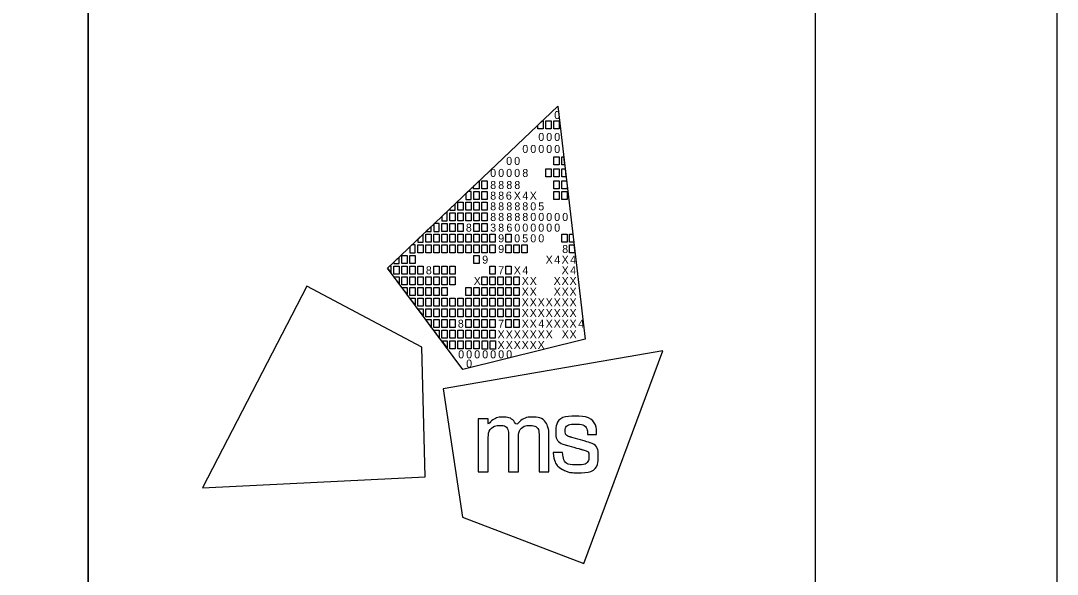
# Model space of a CAD drawing. Extents: x -0.2 to 34, y 0 to 22.
# Drawn here: x 31.86 to 34, y 3.12 to 4.263 of the extents above; entities that cross this region are included whole.
import ezdxf

# ---------------------------------------------------------------- set-up
doc = ezdxf.new("R2010")
doc.units = 0
for name, color, linetype in [('SC_Scratch1', 7, 'Continuous'), ('SH_Border', 7, 'Continuous'), ('SH_Cut_Line', 7, 'Continuous'), ('SH_Data', 7, 'Continuous')]:
    doc.layers.add(name, color=color, linetype=linetype)

msp = doc.modelspace()

# ---------------------------------------------------------------- linework, layer by layer
at = {"layer": 'SC_Scratch1'}
msp.add_lwpolyline([(1.5, 21.5), (32, 21.5), (32, 0.5), (1.5, 0.5)], close=True, dxfattribs=at)
at = {"layer": 'SH_Border'}
msp.add_line((32, 0.5), (32, 21.5), dxfattribs=at)
msp.add_lwpolyline([(1.5, 21.5), (33.5, 21.5), (33.5, 0.5), (1.5, 0.5)], close=True, dxfattribs=at)
at = {"layer": 'SH_Cut_Line'}
msp.add_lwpolyline([(0, 0), (34, 0), (34, 22), (0, 22)], close=True, dxfattribs=at)
at = {"layer": 'SH_Data'}
for p, q in [((32.6175, 3.7519), (32.9688, 4.0861)), ((32.9688, 4.0861), (32.9688, 4.0861)), ((32.9688, 4.0861), (33.0253, 3.6052)), ((32.773, 3.543), (32.6175, 3.7519)), ((33.0253, 3.6052), (32.773, 3.543)), ((32.75, 3.5), (32.75, 3.5))]:
    msp.add_line(p, q, dxfattribs=at)
for points in [[(32.9279, 4.0472), (32.9369, 4.0558), (32.9389, 4.0558), (32.9389, 4.0393), (32.9279, 4.0393)], [(32.9444, 4.0558), (32.9554, 4.0558), (32.9554, 4.0393), (32.9444, 4.0393)], [(32.9609, 4.0558), (32.9719, 4.0558), (32.9719, 4.0393), (32.9609, 4.0393)], [(32.9606, 3.9815), (32.9716, 3.9815), (32.9716, 3.965), (32.9606, 3.965)], [(32.9771, 3.9815), (32.9811, 3.9815), (32.983, 3.965), (32.9771, 3.965)], [(32.9441, 3.9567), (32.9551, 3.9567), (32.9551, 3.9402), (32.9441, 3.9402)], [(32.9606, 3.9567), (32.9716, 3.9567), (32.9716, 3.9402), (32.9606, 3.9402)], [(32.9771, 3.9567), (32.984, 3.9567), (32.9859, 3.9402), (32.9771, 3.9402)], [(32.7953, 3.9211), (32.8064, 3.9316), (32.8064, 3.9154), (32.7953, 3.9154)], [(32.8123, 3.9319), (32.8233, 3.9319), (32.8233, 3.9154), (32.8123, 3.9154)], [(32.9606, 3.9319), (32.9716, 3.9319), (32.9716, 3.9154), (32.9606, 3.9154)], [(32.9771, 3.9319), (32.9869, 3.9319), (32.9881, 3.9218), (32.9881, 3.9154), (32.9771, 3.9154)], [(32.7958, 3.9099), (32.8068, 3.9099), (32.8068, 3.8934), (32.7958, 3.8934)], [(32.8123, 3.9099), (32.8233, 3.9099), (32.8233, 3.8934), (32.8123, 3.8934)], [(32.9606, 3.9099), (32.9716, 3.9099), (32.9716, 3.8934), (32.9606, 3.8934)], [(32.9771, 3.9099), (32.9881, 3.9099), (32.9881, 3.8934), (32.9771, 3.8934)], [(32.7627, 3.8879), (32.7737, 3.8879), (32.7737, 3.8714), (32.7627, 3.8714)], [(32.7793, 3.8879), (32.7903, 3.8879), (32.7903, 3.8714), (32.7793, 3.8714)], [(32.7958, 3.8879), (32.8068, 3.8879), (32.8068, 3.8714), (32.7958, 3.8714)], [(32.8123, 3.8879), (32.8233, 3.8879), (32.8233, 3.8714), (32.8123, 3.8714)], [(32.7462, 3.8659), (32.7572, 3.8659), (32.7572, 3.8494), (32.7462, 3.8494)], [(32.7627, 3.8659), (32.7737, 3.8659), (32.7737, 3.8494), (32.7627, 3.8494)], [(32.7793, 3.8659), (32.7903, 3.8659), (32.7903, 3.8494), (32.7793, 3.8494)], [(32.7958, 3.8659), (32.8068, 3.8659), (32.8068, 3.8494), (32.7958, 3.8494)], [(32.8123, 3.8659), (32.8233, 3.8659), (32.8233, 3.8494), (32.8123, 3.8494)], [(32.7297, 3.8439), (32.7407, 3.8439), (32.7407, 3.8273), (32.7297, 3.8273)], [(32.7462, 3.8439), (32.7572, 3.8439), (32.7572, 3.8273), (32.7462, 3.8273)], [(32.7627, 3.8439), (32.7737, 3.8439), (32.7737, 3.8273), (32.7627, 3.8273)], [(32.7958, 3.8439), (32.8068, 3.8439), (32.8068, 3.8273), (32.7958, 3.8273)], [(32.8123, 3.8439), (32.8233, 3.8439), (32.8233, 3.8273), (32.8123, 3.8273)], [(32.6967, 3.8218), (32.7077, 3.8218), (32.7077, 3.8053), (32.6967, 3.8053)], [(32.7132, 3.8218), (32.7242, 3.8218), (32.7242, 3.8053), (32.7132, 3.8053)], [(32.7297, 3.8218), (32.7407, 3.8218), (32.7407, 3.8053), (32.7297, 3.8053)], [(32.7462, 3.8218), (32.7572, 3.8218), (32.7572, 3.8053), (32.7462, 3.8053)], [(32.7627, 3.8218), (32.7737, 3.8218), (32.7737, 3.8053), (32.7627, 3.8053)], [(32.7793, 3.8218), (32.7903, 3.8218), (32.7903, 3.8053), (32.7793, 3.8053)], [(32.7958, 3.8218), (32.8068, 3.8218), (32.8068, 3.8053), (32.7958, 3.8053)], [(32.8123, 3.8218), (32.8233, 3.8218), (32.8233, 3.8053), (32.8123, 3.8053)], [(32.8288, 3.8218), (32.8398, 3.8218), (32.8398, 3.8053), (32.8288, 3.8053)], [(32.8618, 3.8218), (32.8728, 3.8218), (32.8728, 3.8053), (32.8618, 3.8053)], [(32.9771, 3.8218), (32.9881, 3.8218), (32.9881, 3.8053), (32.9771, 3.8053)], [(32.9935, 3.8218), (32.9998, 3.8218), (33.0018, 3.8053), (32.9935, 3.8053)], [(32.6802, 3.7998), (32.6912, 3.7998), (32.6912, 3.7833), (32.6802, 3.7833)], [(32.6967, 3.7998), (32.7077, 3.7998), (32.7077, 3.7833), (32.6967, 3.7833)], [(32.7132, 3.7998), (32.7242, 3.7998), (32.7242, 3.7833), (32.7132, 3.7833)], [(32.7297, 3.7998), (32.7407, 3.7998), (32.7407, 3.7833), (32.7297, 3.7833)], [(32.7462, 3.7998), (32.7572, 3.7998), (32.7572, 3.7833), (32.7462, 3.7833)], [(32.7627, 3.7998), (32.7737, 3.7998), (32.7737, 3.7833), (32.7627, 3.7833)], [(32.7793, 3.7998), (32.7903, 3.7998), (32.7903, 3.7833), (32.7793, 3.7833)], [(32.7958, 3.7998), (32.8068, 3.7998), (32.8068, 3.7833), (32.7958, 3.7833)], [(32.8123, 3.7998), (32.8233, 3.7998), (32.8233, 3.7833), (32.8123, 3.7833)], [(32.8288, 3.7998), (32.8398, 3.7998), (32.8398, 3.7833), (32.8288, 3.7833)], [(32.8618, 3.7998), (32.8728, 3.7998), (32.8728, 3.7833), (32.8618, 3.7833)], [(32.8783, 3.7998), (32.8893, 3.7998), (32.8893, 3.7833), (32.8783, 3.7833)], [(32.8947, 3.7998), (32.9057, 3.7998), (32.9057, 3.7833), (32.8947, 3.7833)], [(32.9935, 3.7998), (33.0024, 3.7998), (33.0044, 3.7833), (32.9935, 3.7833)], [(32.6471, 3.7778), (32.6581, 3.7778), (32.6581, 3.7613), (32.6471, 3.7613)], [(32.6637, 3.7778), (32.6747, 3.7778), (32.6747, 3.7613), (32.6637, 3.7613)], [(32.7958, 3.7778), (32.8068, 3.7778), (32.8068, 3.7613), (32.7958, 3.7613)], [(32.6306, 3.7558), (32.6416, 3.7558), (32.6416, 3.7393), (32.6306, 3.7393)], [(32.6471, 3.7558), (32.6581, 3.7558), (32.6581, 3.7393), (32.6471, 3.7393)], [(32.6637, 3.7558), (32.6747, 3.7558), (32.6747, 3.7393), (32.6637, 3.7393)], [(32.6802, 3.7558), (32.6912, 3.7558), (32.6912, 3.7393), (32.6802, 3.7393)], [(32.7132, 3.7558), (32.7242, 3.7558), (32.7242, 3.7393), (32.7132, 3.7393)], [(32.7297, 3.7558), (32.7407, 3.7558), (32.7407, 3.7393), (32.7297, 3.7393)], [(32.7462, 3.7558), (32.7572, 3.7558), (32.7572, 3.7393), (32.7462, 3.7393)], [(32.8288, 3.7558), (32.8398, 3.7558), (32.8398, 3.7393), (32.8288, 3.7393)], [(32.8618, 3.7558), (32.8728, 3.7558), (32.8728, 3.7393), (32.8618, 3.7393)], [(32.6306, 3.7338), (32.6416, 3.7338), (32.6416, 3.72)], [(32.6471, 3.7338), (32.6581, 3.7338), (32.6581, 3.7173), (32.6471, 3.7173)], [(32.6637, 3.7338), (32.6747, 3.7338), (32.6747, 3.7173), (32.6637, 3.7173)], [(32.6802, 3.7338), (32.6912, 3.7338), (32.6912, 3.7173), (32.6802, 3.7173)], [(32.6967, 3.7338), (32.7077, 3.7338), (32.7077, 3.7173), (32.6967, 3.7173)], [(32.7132, 3.7338), (32.7242, 3.7338), (32.7242, 3.7173), (32.7132, 3.7173)], [(32.7297, 3.7338), (32.7407, 3.7338), (32.7407, 3.7173), (32.7297, 3.7173)], [(32.7462, 3.7338), (32.7572, 3.7338), (32.7572, 3.7173), (32.7462, 3.7173)], [(32.8123, 3.7338), (32.8233, 3.7338), (32.8233, 3.7173), (32.8123, 3.7173)], [(32.8288, 3.7338), (32.8398, 3.7338), (32.8398, 3.7173), (32.8288, 3.7173)], [(32.8453, 3.7338), (32.8563, 3.7338), (32.8563, 3.7173), (32.8453, 3.7173)], [(32.8618, 3.7338), (32.8728, 3.7338), (32.8728, 3.7173), (32.8618, 3.7173)], [(32.8783, 3.7338), (32.8893, 3.7338), (32.8893, 3.7173), (32.8783, 3.7173)], [(32.6471, 3.7117), (32.6581, 3.7117), (32.6581, 3.698)], [(32.6637, 3.7117), (32.6747, 3.7117), (32.6747, 3.6952), (32.6637, 3.6952)], [(32.6802, 3.7117), (32.6912, 3.7117), (32.6912, 3.6952), (32.6802, 3.6952)], [(32.6967, 3.7117), (32.7077, 3.7117), (32.7077, 3.6952), (32.6967, 3.6952)], [(32.7132, 3.7117), (32.7242, 3.7117), (32.7242, 3.6952), (32.7132, 3.6952)], [(32.7297, 3.7117), (32.7407, 3.7117), (32.7407, 3.6952), (32.7297, 3.6952)], [(32.7793, 3.7117), (32.7903, 3.7117), (32.7903, 3.6952), (32.7793, 3.6952)], [(32.7958, 3.7117), (32.8068, 3.7117), (32.8068, 3.6952), (32.7958, 3.6952)], [(32.8123, 3.7117), (32.8233, 3.7117), (32.8233, 3.6952), (32.8123, 3.6952)], [(32.8288, 3.7117), (32.8398, 3.7117), (32.8398, 3.6952), (32.8288, 3.6952)], [(32.8453, 3.7117), (32.8563, 3.7117), (32.8563, 3.6952), (32.8453, 3.6952)], [(32.8618, 3.7117), (32.8728, 3.7117), (32.8728, 3.6952), (32.8618, 3.6952)], [(32.8783, 3.7117), (32.8893, 3.7117), (32.8893, 3.6952), (32.8783, 3.6952)], [(32.6637, 3.6897), (32.6747, 3.6897), (32.6747, 3.676)], [(32.6747, 3.6897), (32.6747, 3.6897), (32.6747, 3.6897)], [(32.6802, 3.6897), (32.6912, 3.6897), (32.6912, 3.6732), (32.6802, 3.6732)], [(32.6967, 3.6897), (32.7077, 3.6897), (32.7077, 3.6732), (32.6967, 3.6732)], [(32.7132, 3.6897), (32.7242, 3.6897), (32.7242, 3.6732), (32.7132, 3.6732)], [(32.7297, 3.6897), (32.7407, 3.6897), (32.7407, 3.6732), (32.7297, 3.6732)], [(32.7462, 3.6897), (32.7572, 3.6897), (32.7572, 3.6732), (32.7462, 3.6732)], [(32.7627, 3.6897), (32.7737, 3.6897), (32.7737, 3.6732), (32.7627, 3.6732)], [(32.7793, 3.6897), (32.7903, 3.6897), (32.7903, 3.6732), (32.7793, 3.6732)], [(32.7958, 3.6897), (32.8068, 3.6897), (32.8068, 3.6732), (32.7958, 3.6732)], [(32.8123, 3.6897), (32.8233, 3.6897), (32.8233, 3.6732), (32.8123, 3.6732)], [(32.8288, 3.6897), (32.8398, 3.6897), (32.8398, 3.6732), (32.8288, 3.6732)], [(32.8453, 3.6897), (32.8563, 3.6897), (32.8563, 3.6732), (32.8453, 3.6732)], [(32.8618, 3.6897), (32.8728, 3.6897), (32.8728, 3.6732), (32.8618, 3.6732)], [(32.8783, 3.6897), (32.8893, 3.6897), (32.8893, 3.6732), (32.8783, 3.6732)], [(32.6802, 3.6677), (32.6912, 3.6677), (32.6912, 3.654)], [(32.6967, 3.6677), (32.7077, 3.6677), (32.7077, 3.6512), (32.6967, 3.6512)], [(32.7132, 3.6677), (32.7242, 3.6677), (32.7242, 3.6512), (32.7132, 3.6512)], [(32.7297, 3.6677), (32.7407, 3.6677), (32.7407, 3.6512), (32.7297, 3.6512)], [(32.7462, 3.6677), (32.7572, 3.6677), (32.7572, 3.6512), (32.7462, 3.6512)], [(32.7627, 3.6677), (32.7737, 3.6677), (32.7737, 3.6512), (32.7627, 3.6512)], [(32.7793, 3.6677), (32.7903, 3.6677), (32.7903, 3.6512), (32.7793, 3.6512)], [(32.7958, 3.6677), (32.8068, 3.6677), (32.8068, 3.6512), (32.7958, 3.6512)], [(32.8123, 3.6677), (32.8233, 3.6677), (32.8233, 3.6512), (32.8123, 3.6512)], [(32.8288, 3.6677), (32.8398, 3.6677), (32.8398, 3.6512), (32.8288, 3.6512)], [(32.8453, 3.6677), (32.8563, 3.6677), (32.8563, 3.6512), (32.8453, 3.6512)], [(32.8618, 3.6677), (32.8728, 3.6677), (32.8728, 3.6512), (32.8618, 3.6512)], [(32.8783, 3.6677), (32.8893, 3.6677), (32.8893, 3.6512), (32.8783, 3.6512)], [(32.7077, 3.6305), (32.6965, 3.6457), (32.7077, 3.6457)], [(32.7132, 3.6457), (32.7242, 3.6457), (32.7242, 3.6292), (32.7132, 3.6292)], [(32.7297, 3.6457), (32.7407, 3.6457), (32.7407, 3.6292), (32.7297, 3.6292)], [(32.7462, 3.6457), (32.7572, 3.6457), (32.7572, 3.6292), (32.7462, 3.6292)], [(32.7793, 3.6457), (32.7903, 3.6457), (32.7903, 3.6292), (32.7793, 3.6292)], [(32.7958, 3.6457), (32.8068, 3.6457), (32.8068, 3.6292), (32.7958, 3.6292)], [(32.8123, 3.6457), (32.8233, 3.6457), (32.8233, 3.6292), (32.8123, 3.6292)], [(32.8288, 3.6457), (32.8398, 3.6457), (32.8398, 3.6292), (32.8288, 3.6292)], [(32.8618, 3.6457), (32.8728, 3.6457), (32.8728, 3.6292), (32.8618, 3.6292)], [(32.8783, 3.6457), (32.8893, 3.6457), (32.8893, 3.6292), (32.8783, 3.6292)], [(32.724, 3.6082), (32.7132, 3.6237), (32.7242, 3.6237)], [(32.7297, 3.6237), (32.7407, 3.6237), (32.7407, 3.6072), (32.7297, 3.6072)], [(32.7462, 3.6237), (32.7572, 3.6237), (32.7572, 3.6072), (32.7462, 3.6072)], [(32.7627, 3.6237), (32.7737, 3.6237), (32.7737, 3.6072), (32.7627, 3.6072)], [(32.7793, 3.6237), (32.7903, 3.6237), (32.7903, 3.6072), (32.7793, 3.6072)], [(32.7958, 3.6237), (32.8068, 3.6237), (32.8068, 3.6072), (32.7958, 3.6072)], [(32.8123, 3.6237), (32.8233, 3.6237), (32.8233, 3.6072), (32.8123, 3.6072)], [(32.8288, 3.6237), (32.8398, 3.6237), (32.8398, 3.6072), (32.8288, 3.6072)], [(32.7302, 3.6017), (32.7407, 3.6017), (32.7408, 3.5875)], [(32.7463, 3.6017), (32.7573, 3.6017), (32.7573, 3.5852), (32.7463, 3.5852)], [(32.763, 3.6017), (32.774, 3.6017), (32.774, 3.5852), (32.763, 3.5852)], [(32.7794, 3.6017), (32.7904, 3.6017), (32.7904, 3.5852), (32.7794, 3.5852)], [(32.796, 3.6017), (32.807, 3.6017), (32.807, 3.5852), (32.796, 3.5852)], [(32.8129, 3.6017), (32.8239, 3.6017), (32.8239, 3.5851), (32.8129, 3.5851)], [(32.8296, 3.6017), (32.8406, 3.6017), (32.8406, 3.5851), (32.8296, 3.5851)]]:
    msp.add_lwpolyline(points, close=True, dxfattribs=at)
for points in [[(32.7903, 3.9099), (32.7836, 3.9099), (32.7793, 3.9058), (32.7793, 3.8934), (32.7903, 3.8934), (32.7903, 3.9099)], [(32.7572, 3.8849), (32.7462, 3.8744), (32.7462, 3.8714), (32.7572, 3.8714), (32.7572, 3.8849)], [(32.7407, 3.8691), (32.7297, 3.8587), (32.7297, 3.8494), (32.7407, 3.8494), (32.7407, 3.8691)], [(32.7077, 3.8377), (32.6968, 3.8273), (32.7077, 3.8273), (32.7077, 3.8377)], [(32.7242, 3.8439), (32.7141, 3.8439), (32.7132, 3.843), (32.7132, 3.8273), (32.7242, 3.8273), (32.7242, 3.8439)], [(32.6912, 3.822), (32.6802, 3.8115), (32.6802, 3.8053), (32.6912, 3.8053), (32.6912, 3.822)], [(32.6747, 3.7998), (32.6679, 3.7998), (32.6637, 3.7958), (32.6637, 3.7833), (32.6747, 3.7833), (32.6747, 3.7998)], [(32.6416, 3.7749), (32.6306, 3.7644), (32.6306, 3.7613), (32.6416, 3.7613), (32.6416, 3.7749)], [(32.6251, 3.7558), (32.6216, 3.7558), (32.6175, 3.7519), (32.6251, 3.7417), (32.6251, 3.7558)], [(32.4512, 3.7149), (32.2359, 3.2988), (32.6956, 3.3215), (32.6884, 3.5892), (32.4512, 3.7149)], [(33.0229, 3.1422), (33.1859, 3.5814), (32.7324, 3.5029), (32.7722, 3.2381), (33.0229, 3.1422)]]:
    msp.add_lwpolyline(points, dxfattribs=at)
for points in [[(32.9595, 3.3709), (32.9595, 3.3709), (32.9595, 3.3717), (32.9595, 3.3717), (32.9595, 3.3717), (32.9603, 3.3717), (32.9603, 3.3717), (32.9603, 3.3717), (32.9783, 3.3717), (32.9783, 3.3717), (32.9783, 3.3717), (32.9789, 3.3717), (32.9789, 3.3717), (32.9789, 3.3717), (32.979, 3.371), (32.979, 3.371), (32.9803, 3.3554), (32.9887, 3.346), (33.009, 3.346), (33.0273, 3.346), (33.0333, 3.3554), (33.0333, 3.3631), (33.0333, 3.3732), (33.0256, 3.3758), (33.0175, 3.378), (33.0175, 3.378), (32.987, 3.3867), (32.987, 3.3867), (32.972, 3.3909), (32.9648, 3.4019), (32.9648, 3.4142), (32.9648, 3.4303), (32.9768, 3.4462), (33.0052, 3.4462), (33.0348, 3.4462), (33.0489, 3.4285), (33.0489, 3.4095), (33.0489, 3.4095), (33.0489, 3.4087), (33.0489, 3.4087), (33.0489, 3.4087), (33.0482, 3.4087), (33.0482, 3.4087), (33.0482, 3.4087), (33.0312, 3.4087), (33.0312, 3.4087), (33.0312, 3.4087), (33.0305, 3.4087), (33.0305, 3.4087), (33.0305, 3.4087), (33.0305, 3.4094), (33.0305, 3.4094), (33.0301, 3.4208), (33.0226, 3.43), (33.0056, 3.43), (32.9891, 3.43), (32.9843, 3.4218), (32.9843, 3.4157), (32.9843, 3.4108), (32.9869, 3.4059), (32.9959, 3.4033), (32.9959, 3.4033), (33.0255, 3.3948), (33.0255, 3.3948), (33.0462, 3.3889), (33.0527, 3.3777), (33.0527, 3.3639), (33.0527, 3.3462), (33.041, 3.3298), (33.0087, 3.3298), (32.9952, 3.3298), (32.9877, 3.3321), (32.9823, 3.3348), (32.969, 3.3414), (32.9609, 3.3536), (32.9595, 3.3709)], [(32.8048, 3.3315), (32.8048, 3.3315), (32.8048, 3.4409), (32.8048, 3.4409), (32.8048, 3.4409), (32.8255, 3.4409), (32.8255, 3.4409), (32.8255, 3.4409), (32.8255, 3.4297), (32.8255, 3.4297), (32.8346, 3.4399), (32.8457, 3.4445), (32.8555, 3.4445), (32.8688, 3.4445), (32.8791, 3.4372), (32.8837, 3.4266), (32.8915, 3.4381), (32.905, 3.4446), (32.9166, 3.4446), (32.9325, 3.4446), (32.9451, 3.435), (32.9494, 3.4213), (32.9494, 3.4212), (32.9494, 3.4212), (32.9494, 3.4212), (32.9501, 3.419), (32.9506, 3.4172), (32.9506, 3.4071), (32.9506, 3.4071), (32.9506, 3.3314), (32.9506, 3.3314), (32.9506, 3.3314), (32.9303, 3.3314), (32.9303, 3.3314), (32.9303, 3.3314), (32.9303, 3.4048), (32.9303, 3.4048), (32.9303, 3.4201), (32.9219, 3.4274), (32.911, 3.4274), (32.8995, 3.4274), (32.8879, 3.4171), (32.8879, 3.4001), (32.8879, 3.4001), (32.8879, 3.3315), (32.8879, 3.3315), (32.8879, 3.3315), (32.8674, 3.3315), (32.8674, 3.3315), (32.8674, 3.3315), (32.8674, 3.4059), (32.8674, 3.4059), (32.8674, 3.4203), (32.8588, 3.4274), (32.8496, 3.4274), (32.8384, 3.4274), (32.8254, 3.417), (32.8254, 3.3962), (32.8254, 3.3962), (32.8254, 3.3315), (32.8254, 3.3315), (32.8254, 3.3315), (32.8048, 3.3315), (32.8048, 3.3315)]]:
    msp.add_open_spline(points, degree=3, dxfattribs=at)

# ---------------------------------------------------------------- texts
for s, p in [('0', (32.9617, 4.0597)), ('0', (32.9288, 4.0145)), ('0', (32.9452, 4.0145)), ('0', (32.9617, 4.0145)), ('0', (32.8958, 3.9897)), ('0', (32.9123, 3.9897)), ('0', (32.9288, 3.9897)), ('0', (32.9452, 3.9897)), ('0', (32.9617, 3.9897)), ('0', (32.8625, 3.965)), ('0', (32.879, 3.965)), ('0', (32.8295, 3.9402)), ('0', (32.846, 3.9402)), ('0', (32.8625, 3.9402)), ('0', (32.879, 3.9402)), ('8', (32.8958, 3.9402)), ('8', (32.8295, 3.9154)), ('8', (32.846, 3.9154)), ('8', (32.8628, 3.9154)), ('8', (32.8793, 3.9154)), ('8', (32.8295, 3.8934)), ('8', (32.846, 3.8934)), ('6', (32.8618, 3.8934)), ('X', (32.8781, 3.8934)), ('4', (32.8958, 3.8934)), ('X', (32.911, 3.8934)), ('8', (32.8295, 3.8713)), ('8', (32.846, 3.8713)), ('8', (32.8628, 3.8713)), ('8', (32.8794, 3.8713)), ('8', (32.8958, 3.8713)), ('0', (32.9123, 3.8713)), ('5', (32.9287, 3.8713)), ('8', (32.8295, 3.8494)), ('8', (32.846, 3.8494)), ('8', (32.8628, 3.8494)), ('8', (32.8794, 3.8494)), ('8', (32.8958, 3.8494)), ('0', (32.9123, 3.8494)), ('0', (32.9288, 3.8494)), ('0', (32.9452, 3.8494)), ('0', (32.9617, 3.8494)), ('0', (32.9782, 3.8494)), ('8', (32.7793, 3.8273)), ('3', (32.8295, 3.8273)), ('8', (32.846, 3.8273)), ('6', (32.8629, 3.8273)), ('0', (32.8793, 3.8273)), ('0', (32.8958, 3.8273)), ('0', (32.9123, 3.8273)), ('0', (32.9288, 3.8273)), ('0', (32.9452, 3.8273)), ('0', (32.9617, 3.8273)), ('9', (32.846, 3.8053)), ('0', (32.879, 3.8053)), ('5', (32.8957, 3.8053)), ('0', (32.9123, 3.8053)), ('0', (32.9288, 3.8053)), ('9', (32.846, 3.7833)), ('8', (32.9781, 3.7833)), ('9', (32.813, 3.7613)), ('X', (32.9439, 3.7613)), ('4', (32.9617, 3.7613)), ('X', (32.9769, 3.7613)), ('4', (32.9946, 3.7613)), ('8', (32.6967, 3.7393)), ('7', (32.846, 3.7393)), ('X', (32.8781, 3.7393)), ('4', (32.8958, 3.7393)), ('X', (32.9769, 3.7393)), ('4', (32.9946, 3.7393)), ('X', (32.7955, 3.7173)), ('X', (32.8945, 3.7173)), ('X', (32.911, 3.7173)), ('X', (32.9604, 3.7173)), ('X', (32.9769, 3.7173)), ('X', (32.9933, 3.7173)), ('X', (32.8945, 3.6952)), ('X', (32.911, 3.6952)), ('X', (32.9604, 3.6952)), ('X', (32.9769, 3.6952)), ('X', (32.9933, 3.6952)), ('X', (32.8945, 3.6732)), ('X', (32.911, 3.6732)), ('X', (32.9274, 3.6732)), ('X', (32.9439, 3.6732)), ('X', (32.9604, 3.6732)), ('X', (32.9769, 3.6732)), ('X', (32.9933, 3.6732)), ('X', (32.8945, 3.6512)), ('X', (32.911, 3.6512)), ('X', (32.9274, 3.6512)), ('X', (32.9439, 3.6512)), ('X', (32.9604, 3.6512)), ('X', (32.9769, 3.6512)), ('X', (32.9933, 3.6512)), ('8', (32.7627, 3.6292)), ('7', (32.846, 3.6292)), ('X', (32.8945, 3.6292)), ('X', (32.911, 3.6292)), ('4', (32.9288, 3.6292)), ('X', (32.9439, 3.6292)), ('X', (32.9604, 3.6292)), ('X', (32.9769, 3.6292)), ('X', (32.9933, 3.6292)), ('4', (33.0111, 3.6292)), ('X', (32.8447, 3.6072)), ('X', (32.8616, 3.6072)), ('X', (32.878, 3.6072)), ('X', (32.8945, 3.6072)), ('X', (32.911, 3.6072)), ('X', (32.9274, 3.6072)), ('X', (32.9439, 3.6072)), ('X', (32.9771, 3.6072)), ('X', (32.9933, 3.6072)), ('X', (32.8447, 3.5851)), ('X', (32.8616, 3.5851)), ('X', (32.878, 3.5851)), ('X', (32.8945, 3.5851)), ('X', (32.911, 3.5851)), ('X', (32.9274, 3.5851)), ('0', (32.7634, 3.5659)), ('0', (32.7799, 3.5659)), ('0', (32.7965, 3.5659)), ('0', (32.813, 3.5659)), ('0', (32.8295, 3.5659)), ('0', (32.846, 3.5659)), ('0', (32.8625, 3.5659)), ('0', (32.7799, 3.5467))]:
    msp.add_text(s, height=0.0165, rotation=360, dxfattribs=at).set_placement(p)

doc.saveas('drawing.dxf')
